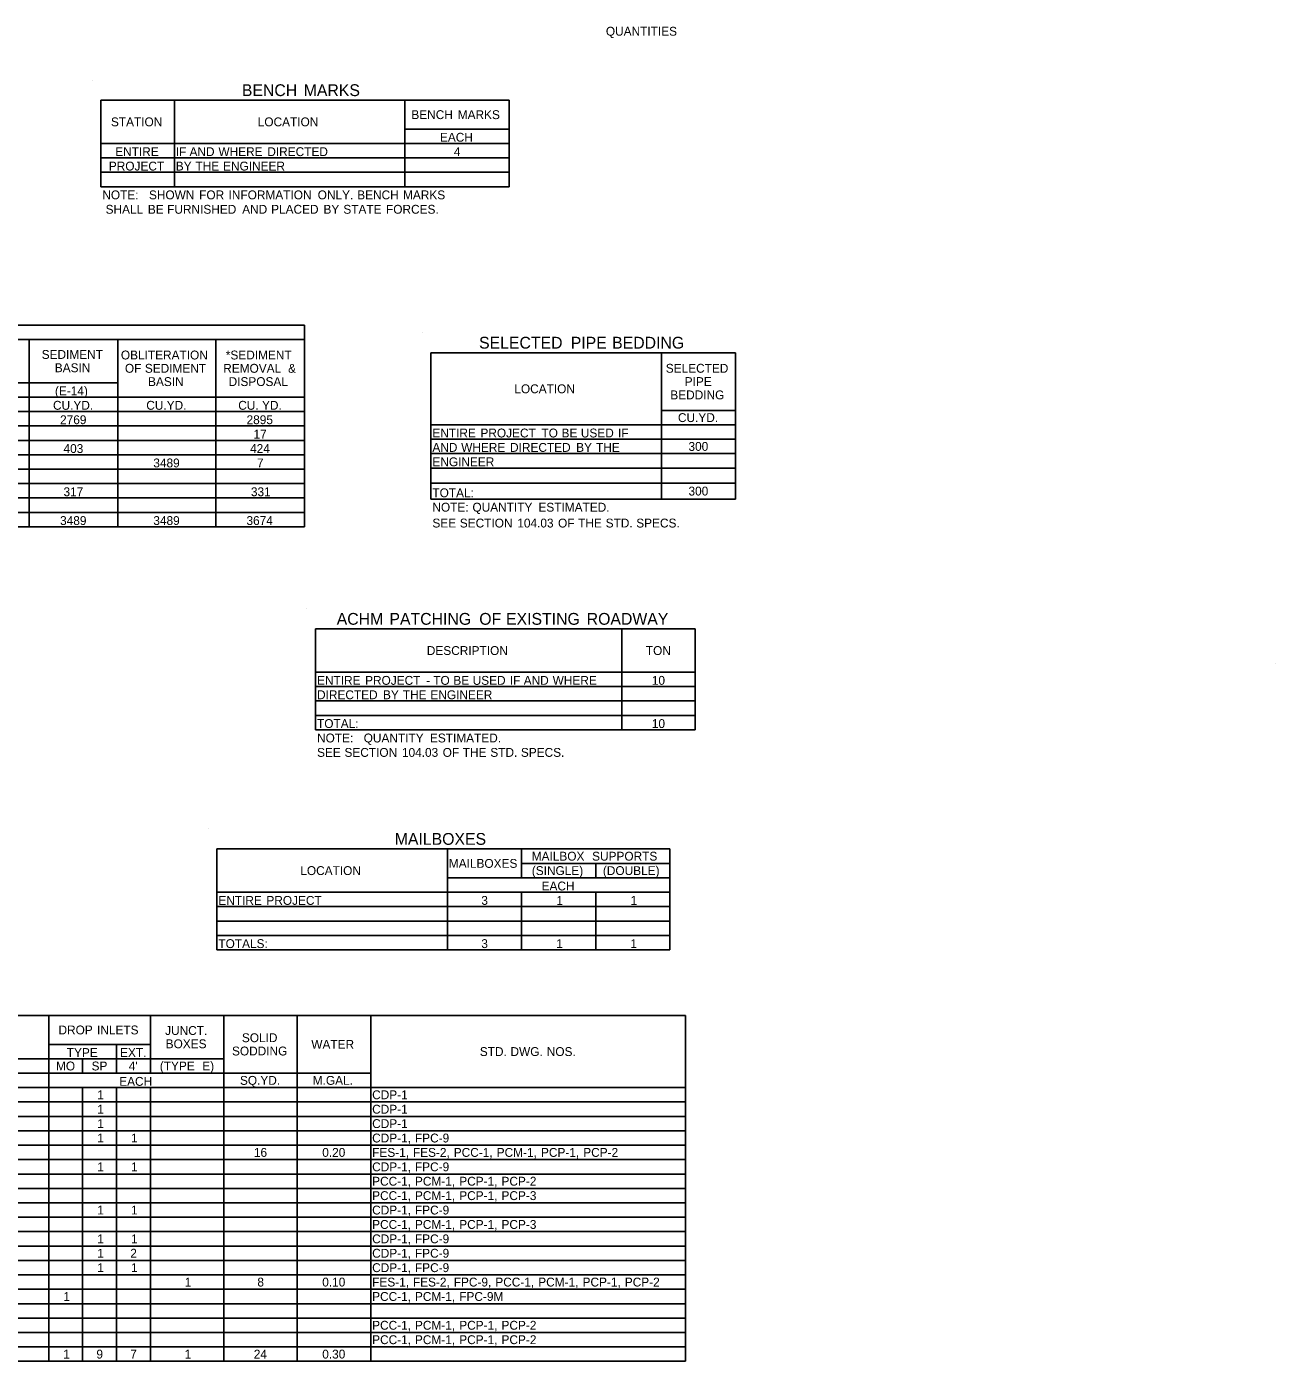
# Model space of a CAD drawing. Extents: x 1197542 to 1207068, y 230488 to 237324.
# Drawn here: x 1200869 to 1201714, y 231809 to 232712 of the extents above; entities that cross this region are included whole.
import ezdxf

# ---------------------------------------------------------------- set-up
doc = ezdxf.new("R2010")
doc.units = 0
doc.layers.add('Default', color=7, linetype='Continuous')
doc.layers.add('R_Border', color=7, linetype='Continuous')

msp = doc.modelspace()

# ---------------------------------------------------------------- linework, layer by layer
at = {"layer": 'Default'}
for p, q in [((1200913.02, 232675.98), (1200913.02, 232675.98)), ((1200918.87, 232662.33), (1201195.29, 232662.33)), ((1200918.87, 232603.83), (1200918.87, 232662.33)), ((1200918.87, 232603.83), (1200918.87, 232662.33)), ((1200968.6, 232603.83), (1200968.6, 232662.33)), ((1201124.6, 232603.83), (1201124.6, 232662.33)), ((1201195.29, 232603.83), (1201195.29, 232662.33)), ((1201124.6, 232642.83), (1201195.29, 232642.83)), ((1201195.29, 232603.83), (1201195.29, 232642.83)), ((1200918.87, 232633.08), (1201195.29, 232633.08)), ((1201124.6, 232603.83), (1201124.6, 232633.08)), ((1200918.87, 232623.33), (1201195.29, 232623.33)), ((1200918.87, 232613.58), (1201195.29, 232613.58)), ((1200918.87, 232603.83), (1201195.29, 232603.83)), ((1199844.22, 232510.16), (1201056.63, 232510.16)), ((1201056.63, 232373.66), (1201056.63, 232510.16)), ((1200165.48, 232500.41), (1201056.63, 232500.41)), ((1200870.4, 232373.66), (1200870.4, 232500.41)), ((1200930.37, 232373.66), (1200930.37, 232500.41)), ((1200996.67, 232373.66), (1200996.67, 232500.41)), ((1201136.44, 232505.07), (1201136.44, 232505.07)), ((1201142.29, 232491.42), (1201348.51, 232491.42)), ((1201142.29, 232392.45), (1201142.29, 232491.42)), ((1201142.29, 232392.45), (1201142.29, 232491.42)), ((1201298.29, 232392.45), (1201298.29, 232491.42)), ((1201348.51, 232392.45), (1201348.51, 232491.42)), ((1201348.51, 232392.45), (1201348.51, 232491.42)), ((1200637.87, 232471.16), (1200930.37, 232471.16)), ((1200820.19, 232471.16), (1200930.37, 232471.16)), ((1200165.48, 232461.41), (1201056.63, 232461.41)), ((1200870.4, 232373.66), (1200870.4, 232461.41)), ((1200930.37, 232461.41), (1201056.63, 232461.41)), ((1200930.37, 232373.66), (1200930.37, 232461.41)), ((1200996.67, 232393.16), (1200996.67, 232461.41)), ((1199844.22, 232451.66), (1201056.63, 232451.66)), ((1201056.63, 232383.41), (1201056.63, 232451.66)), ((1201298.29, 232452.42), (1201348.51, 232452.42)), ((1199844.22, 232441.91), (1201056.63, 232441.91)), ((1201142.29, 232442.67), (1201348.51, 232442.67)), ((1201298.29, 232392.45), (1201298.29, 232442.67)), ((1199844.22, 232432.16), (1201056.63, 232432.16)), ((1201142.29, 232432.92), (1201348.51, 232432.92)), ((1199844.22, 232422.41), (1201056.63, 232422.41)), ((1201142.29, 232423.17), (1201348.51, 232423.17)), ((1199844.22, 232412.66), (1201056.63, 232412.66)), ((1201142.29, 232413.42), (1201348.51, 232413.42)), ((1199844.22, 232402.91), (1201056.63, 232402.91)), ((1201142.29, 232403.18), (1201348.51, 232403.18)), ((1199844.22, 232393.16), (1201056.63, 232393.16)), ((1201142.29, 232392.45), (1201348.51, 232392.45)), ((1199844.22, 232383.41), (1201056.63, 232383.41)), ((1200759.74, 232383.41), (1200996.67, 232383.41)), ((1200996.67, 232383.41), (1201056.63, 232383.41)), ((1200996.67, 232373.66), (1200996.67, 232383.41)), ((1199844.22, 232373.66), (1201056.63, 232373.66)), ((1201058.36, 232318.16), (1201058.36, 232318.16)), ((1201064.21, 232304.51), (1201321.13, 232304.51)), ((1201064.21, 232236.26), (1201064.21, 232304.51)), ((1201064.21, 232236.26), (1201064.21, 232304.51)), ((1201271.4, 232236.26), (1201271.4, 232304.51)), ((1201321.13, 232236.26), (1201321.13, 232304.51)), ((1201064.21, 232275.26), (1201321.13, 232275.26)), ((1201271.4, 232236.26), (1201271.4, 232275.26)), ((1201321.13, 232236.26), (1201321.13, 232275.26)), ((1201713.82, 232281.1), (1201713.82, 232281.1)), ((1201064.21, 232265.51), (1201321.13, 232265.51)), ((1201064.21, 232255.76), (1201321.13, 232255.76)), ((1201064.21, 232246.01), (1201321.13, 232246.01)), ((1201064.21, 232236.26), (1201321.13, 232236.26)), ((1200991.57, 232169.24), (1200991.57, 232169.24)), ((1200997.42, 232155.59), (1201304.06, 232155.59)), ((1200997.42, 232087.34), (1200997.42, 232155.59)), ((1200997.42, 232087.34), (1200997.42, 232155.59)), ((1201153.42, 232087.34), (1201153.42, 232155.59)), ((1201203.63, 232136.09), (1201203.63, 232155.59)), ((1201304.06, 232087.34), (1201304.06, 232155.59)), ((1201203.63, 232145.84), (1201304.06, 232145.84)), ((1201253.85, 232136.09), (1201253.85, 232145.84)), ((1201153.42, 232136.09), (1201304.06, 232136.09)), ((1201203.63, 232136.09), (1201304.06, 232136.09)), ((1200997.42, 232126.34), (1201304.06, 232126.34)), ((1201153.42, 232087.34), (1201153.42, 232126.34)), ((1201203.63, 232087.34), (1201203.63, 232126.34)), ((1201203.63, 232087.34), (1201203.63, 232126.34)), ((1201253.85, 232087.34), (1201253.85, 232126.34)), ((1201253.85, 232087.34), (1201253.85, 232126.34)), ((1201304.06, 232087.34), (1201304.06, 232126.34)), ((1200997.42, 232116.59), (1201304.06, 232116.59)), ((1200997.42, 232106.84), (1201304.06, 232106.84)), ((1200997.42, 232097.09), (1201304.06, 232097.09)), ((1200997.42, 232087.34), (1201304.06, 232087.34)), ((1200342, 232042.86), (1201314.56, 232042.86)), ((1200883.61, 231808.86), (1200883.61, 232042.86)), ((1200952.35, 232003.86), (1200952.35, 232042.86)), ((1200952.35, 232003.86), (1200952.35, 232042.86)), ((1201002.07, 231808.86), (1201002.07, 232042.86)), ((1201051.8, 231808.86), (1201051.8, 232042.86)), ((1201101.52, 231808.86), (1201101.52, 232042.86)), ((1201314.56, 231808.86), (1201314.56, 232042.86)), ((1200883.61, 232023.36), (1200952.35, 232023.36)), ((1200929.43, 232003.86), (1200929.43, 232023.36)), ((1200555.03, 232013.61), (1200952.35, 232013.61)), ((1200883.61, 231808.86), (1200883.61, 232013.61)), ((1200906.52, 232003.86), (1200906.52, 232013.61)), ((1200906.52, 232003.86), (1200906.52, 232013.61)), ((1200929.43, 232003.86), (1200929.43, 232013.61)), ((1200952.35, 232013.61), (1201002.07, 232013.61)), ((1201002.07, 232003.86), (1201002.07, 232013.61)), ((1200504.82, 232003.86), (1200952.35, 232003.86)), ((1200883.61, 232003.86), (1201101.52, 232003.86)), ((1201051.8, 231808.86), (1201051.8, 232003.86)), ((1201101.52, 231808.86), (1201101.52, 232003.86)), ((1200342, 231994.11), (1201314.56, 231994.11)), ((1200906.52, 231808.86), (1200906.52, 231994.11)), ((1200906.52, 231808.86), (1200906.52, 231994.11)), ((1200929.43, 231808.86), (1200929.43, 231994.11)), ((1200929.43, 231808.86), (1200929.43, 231994.11)), ((1200952.35, 231808.86), (1200952.35, 231994.11)), ((1200952.35, 231808.86), (1200952.35, 231994.11)), ((1201002.07, 231808.86), (1201002.07, 231994.11)), ((1201101.52, 231994.11), (1201314.56, 231994.11)), ((1200342, 231984.36), (1201314.56, 231984.36)), ((1201101.52, 231984.36), (1201314.56, 231984.36)), ((1200342, 231974.61), (1201314.56, 231974.61)), ((1201101.52, 231974.61), (1201314.56, 231974.61)), ((1200342, 231964.86), (1201314.56, 231964.86)), ((1200342, 231955.11), (1201314.56, 231955.11)), ((1201101.52, 231955.11), (1201314.56, 231955.11)), ((1200342, 231945.36), (1201314.56, 231945.36)), ((1201101.52, 231945.36), (1201314.56, 231945.36)), ((1200342, 231935.61), (1201314.56, 231935.61)), ((1200342, 231925.86), (1201314.56, 231925.86)), ((1201101.52, 231925.86), (1201314.56, 231925.86)), ((1200342, 231916.11), (1201314.56, 231916.11)), ((1201101.52, 231916.11), (1201314.56, 231916.11)), ((1200342, 231906.36), (1201314.56, 231906.36)), ((1201101.52, 231906.36), (1201314.56, 231906.36)), ((1200342, 231896.61), (1201314.56, 231896.61)), ((1201101.52, 231896.61), (1201314.56, 231896.61)), ((1200342, 231886.86), (1201314.56, 231886.86)), ((1201101.52, 231886.86), (1201314.56, 231886.86)), ((1200342, 231877.11), (1201314.56, 231877.11)), ((1201101.52, 231877.11), (1201314.56, 231877.11)), ((1200342, 231867.36), (1201314.56, 231867.36)), ((1201101.52, 231867.36), (1201314.56, 231867.36)), ((1200342, 231857.61), (1201314.56, 231857.61)), ((1201101.52, 231857.61), (1201314.56, 231857.61)), ((1200342, 231847.86), (1201314.56, 231847.86)), ((1201101.52, 231847.86), (1201314.56, 231847.86)), ((1200342, 231838.11), (1201314.56, 231838.11)), ((1200342, 231828.36), (1201314.56, 231828.36)), ((1201101.52, 231828.36), (1201314.56, 231828.36)), ((1200342, 231818.61), (1201101.52, 231818.61)), ((1201101.52, 231818.61), (1201314.56, 231818.61)), ((1201314.56, 231808.86), (1201314.56, 231818.61)), ((1200342, 231808.86), (1201314.56, 231808.86))]:
    msp.add_line(p, q, dxfattribs=at)

# ---------------------------------------------------------------- texts
for s, height, p in [('BENCH', 8, (1201014.31, 232665.15)), (' MARKS', 8, (1201053.2, 232665.15)), ('BENCH', 6, (1201129.03, 232649.58)), (' MARKS', 6, (1201158.2, 232649.58)), ('STATION', 6, (1200925.68, 232644.7)), ('LOCATION', 6, (1201025.05, 232644.7)), ('EACH', 6, (1201148.39, 232634.28)), ('ENTIRE', 6, (1200928.59, 232624.53)), ('IF', 6, (1200969.57, 232624.53)), (' AND', 6, (1200976.64, 232624.53)), (' WHERE', 6, (1200996.22, 232624.53)), (' DIRECTED', 6, (1201029.31, 232624.53)), ('4', 6, (1201157.82, 232624.53)), ('PROJECT', 6, (1200924.26, 232614.78)), ('BY', 6, (1200969.57, 232614.78)), (' THE', 6, (1200980.7, 232614.78)), (' ENGINEER', 6, (1200999.35, 232614.78)), ('NOTE:', 6, (1200919.85, 232595.28)), ('   SHOWN', 6, (1200944.74, 232595.28)), (' FOR', 6, (1200983.17, 232595.28)), (' INFORMATION', 6, (1201003.08, 232595.28)), (' ONLY.', 6, (1201063.41, 232595.28)), (' BENCH', 6, (1201090.16, 232595.28)), (' MARKS', 6, (1201121.16, 232595.28)), (' SHALL', 6, (1200919.85, 232585.53)), (' BE', 6, (1200948.44, 232585.53)), (' FURNISHED', 6, (1200961.51, 232585.53)), (' AND', 6, (1201012.3, 232585.53)), (' PLACED', 6, (1201031.88, 232585.53)), (' BY', 6, (1201067.31, 232585.53)), (' STATE', 6, (1201080.76, 232585.53)), (' FORCES.', 6, (1201109.66, 232585.53)), ('SELECTED', 8, (1201174.86, 232494.24)), (' PIPE', 8, (1201233.94, 232494.24)), (' BEDDING', 8, (1201261.96, 232494.24)), ('SEDIMENT', 6, (1200878.81, 232487.29)), ('OBLITERATION', 6, (1200932.41, 232486.91)), ('*SEDIMENT', 6, (1201003.44, 232486.91)), ('BASIN', 6, (1200887.68, 232478.29)), ('OF', 6, (1200935.15, 232477.91)), (' SEDIMENT', 6, (1200946.41, 232477.91)), ('REMOVAL', 6, (1201001.69, 232477.91)), (' &', 6, (1201043.36, 232477.91)), ('SELECTED', 6, (1201301.25, 232477.92)), ('BASIN', 6, (1200950.81, 232468.91)), ('DISPOSAL', 6, (1201005.34, 232468.91)), ('PIPE', 6, (1201314.06, 232468.92)), ('(E-14)', 6, (1200887.8, 232462.61)), ('LOCATION', 6, (1201198.74, 232464.04)), ('BEDDING', 6, (1201304.32, 232459.92)), ('CU.YD.', 6, (1200886.47, 232452.86)), ('CU.YD.', 6, (1200949.6, 232452.86)), ('CU.', 6, (1201011.85, 232452.86)), (' YD.', 6, (1201025.71, 232452.86)), ('2769', 6, (1200891.25, 232443.11)), ('2895', 6, (1201017.49, 232443.11)), ('CU.YD.', 6, (1201309.48, 232444.54)), ('17', 6, (1201022.18, 232433.36)), ('ENTIRE', 6, (1201143.27, 232434.12)), (' PROJECT', 6, (1201173.57, 232434.12)), (' TO', 6, (1201214.86, 232434.12)), (' BE', 6, (1201228.45, 232434.12)), (' USED', 6, (1201241.52, 232434.12)), (' IF', 6, (1201266.69, 232434.12)), ('403', 6, (1200893.58, 232423.61)), ('424', 6, (1201019.86, 232423.61)), ('AND', 6, (1201143.27, 232424.37)), (' WHERE', 6, (1201160.52, 232424.37)), (' DIRECTED', 6, (1201193.61, 232424.37)), (' BY', 6, (1201238.35, 232424.37)), (' THE', 6, (1201251.8, 232424.37)), ('300', 6, (1201316.61, 232425.04)), ('3489', 6, (1200954.38, 232413.86)), ('7', 6, (1201024.51, 232413.86)), ('ENGINEER', 6, (1201143.27, 232414.62)), ('317', 6, (1200893.58, 232394.36)), ('331', 6, (1201020.43, 232394.36)), ('TOTAL:', 6, (1201143.27, 232393.65)), ('300', 6, (1201316.62, 232394.82)), ('NOTE:', 6, (1201143.27, 232383.9)), (' QUANTITY', 6, (1201168.16, 232383.9)), (' ESTIMATED.', 6, (1201212.81, 232383.9)), ('3489', 6, (1200891.26, 232374.86)), ('3489', 6, (1200954.39, 232374.86)), ('3674', 6, (1201017.42, 232374.86)), ('SEE', 6, (1201143.27, 232373.18)), (' SECTION', 6, (1201159.6, 232373.18)), (' 104.03', 6, (1201198.51, 232373.18)), (' OF', 6, (1201226.09, 232373.18)), (' THE', 6, (1201239.67, 232373.18)), (' STD.', 6, (1201258.32, 232373.18)), (' SPECS.', 6, (1201279.02, 232373.18)), ('ACHM', 8, (1201078.49, 232307.34)), (' PATCHING', 8, (1201111.22, 232307.34)), (' OF', 8, (1201172.02, 232307.34)), (' EXISTING', 8, (1201190.13, 232307.34)), (' ROADWAY', 8, (1201244.74, 232307.34)), ('DESCRIPTION', 6, (1201139.5, 232286.89)), ('TON', 6, (1201287.75, 232286.89)), ('ENTIRE', 6, (1201065.19, 232266.71)), (' PROJECT', 6, (1201095.49, 232266.71)), (' -', 6, (1201136.78, 232266.71)), (' TO', 6, (1201141.63, 232266.71)), (' BE', 6, (1201155.23, 232266.71)), (' USED', 6, (1201168.3, 232266.71)), (' IF', 6, (1201193.47, 232266.71)), (' AND', 6, (1201202.86, 232266.71)), (' WHERE', 6, (1201222.45, 232266.71)), ('10', 6, (1201291.81, 232266.71)), ('DIRECTED', 6, (1201065.19, 232256.96)), (' BY', 6, (1201107.6, 232256.96)), (' THE', 6, (1201121.05, 232256.96)), (' ENGINEER', 6, (1201139.7, 232256.96)), ('TOTAL:', 6, (1201065.19, 232237.46)), ('10', 6, (1201291.81, 232237.46)), ('NOTE:', 6, (1201065.19, 232227.71)), ('   QUANTITY', 6, (1201090.08, 232227.71)), (' ESTIMATED.', 6, (1201139.38, 232227.71)), ('SEE', 6, (1201065.19, 232217.96)), (' SECTION', 6, (1201081.52, 232217.96)), (' 104.03', 6, (1201120.43, 232217.96)), (' OF', 6, (1201148.01, 232217.96)), (' THE', 6, (1201161.59, 232217.96)), (' STD.', 6, (1201180.24, 232217.96)), (' SPECS.', 6, (1201200.94, 232217.96)), ('MAILBOXES', 8, (1201117.79, 232158.41)), ('MAILBOXES', 6, (1201154.4, 232142.84)), ('MAILBOX', 6, (1201210.5, 232147.71)), (' SUPPORTS', 6, (1201249.15, 232147.71)), ('LOCATION', 6, (1201053.87, 232137.96)), ('(SINGLE)', 6, (1201210.56, 232137.96)), ('(DOUBLE)', 6, (1201258.68, 232137.96)), ('EACH', 6, (1201217.18, 232127.54)), ('ENTIRE', 6, (1200998.4, 232117.79)), (' PROJECT', 6, (1201028.69, 232117.79)), ('3', 6, (1201176.39, 232117.79)), ('1', 6, (1201227.18, 232117.79)), ('1', 6, (1201277.39, 232117.79)), ('TOTALS:', 6, (1200998.4, 232088.54)), ('3', 6, (1201176.38, 232088.54)), ('1', 6, (1201227.09, 232088.54)), ('1', 6, (1201277.3, 232088.54)), ('DROP', 6, (1200890.19, 232030.11)), (' INLETS', 6, (1200914.03, 232030.11)), ('JUNCT.', 6, (1200962.36, 232029.73)), ('SOLID', 6, (1201014.33, 232024.86)), ('TYPE', 6, (1200895.78, 232014.81)), ('EXT.', 6, (1200931.86, 232014.81)), ('BOXES', 6, (1200962.74, 232020.73)), ('SODDING', 6, (1201007.62, 232015.86)), ('WATER', 6, (1201061.31, 232020.36)), ('STD.', 6, (1201175.37, 232015.48)), (' DWG.', 6, (1201193.89, 232015.48)), (' NOS.', 6, (1201218.46, 232015.48)), ('MO', 6, (1200888.48, 232005.73)), ('SP', 6, (1200912.58, 232005.73)), ("4'", 6, (1200937.75, 232005.73)), ('(TYPE', 6, (1200958.77, 232005.73)), ('  E)', 6, (1200983.04, 232005.73)), ('EACH', 6, (1200931.28, 231995.31)), ('SQ.YD.', 6, (1201013.01, 231995.98)), ('M.GAL.', 6, (1201062.28, 231995.98)), ('1', 6, (1200916.42, 231986.23)), ('CDP-1', 6, (1201102.5, 231986.23)), ('1', 6, (1200916.42, 231976.48)), ('CDP-1', 6, (1201102.5, 231976.48)), ('1', 6, (1200916.42, 231966.73)), ('CDP-1', 6, (1201102.5, 231966.73)), ('1', 6, (1200916.42, 231956.98)), ('1', 6, (1200939.33, 231956.98)), ('CDP-1,', 6, (1201102.5, 231956.98)), (' FPC-9', 6, (1201129.23, 231956.98)), ('16', 6, (1201022.46, 231947.23)), ('0.20', 6, (1201068.71, 231947.23)), ('FES-1,', 6, (1201102.5, 231947.23)), (' FES-2,', 6, (1201127.84, 231947.23)), (' PCC-1,', 6, (1201155.5, 231947.23)), (' PCM-1,', 6, (1201184.57, 231947.23)), (' PCP-1,', 6, (1201214.56, 231947.23)), (' PCP-2', 6, (1201243.16, 231947.23)), ('1', 6, (1200916.42, 231937.48)), ('1', 6, (1200939.33, 231937.48)), ('CDP-1,', 6, (1201102.5, 231937.48)), (' FPC-9', 6, (1201129.23, 231937.48)), ('PCC-1,', 6, (1201102.5, 231927.73)), (' PCM-1,', 6, (1201129.23, 231927.73)), (' PCP-1,', 6, (1201159.22, 231927.73)), (' PCP-2', 6, (1201187.82, 231927.73)), ('PCC-1,', 6, (1201102.5, 231917.98)), (' PCM-1,', 6, (1201129.23, 231917.98)), (' PCP-1,', 6, (1201159.22, 231917.98)), (' PCP-3', 6, (1201187.82, 231917.98)), ('1', 6, (1200916.42, 231908.23)), ('1', 6, (1200939.33, 231908.23)), ('CDP-1,', 6, (1201102.5, 231908.23)), (' FPC-9', 6, (1201129.23, 231908.23)), ('PCC-1,', 6, (1201102.5, 231898.48)), (' PCM-1,', 6, (1201129.23, 231898.48)), (' PCP-1,', 6, (1201159.22, 231898.48)), (' PCP-3', 6, (1201187.82, 231898.48)), ('1', 6, (1200916.42, 231888.73)), ('1', 6, (1200939.33, 231888.73)), ('CDP-1,', 6, (1201102.5, 231888.73)), (' FPC-9', 6, (1201129.23, 231888.73)), ('1', 6, (1200916.42, 231878.98)), ('2', 6, (1200938.78, 231878.98)), ('CDP-1,', 6, (1201102.5, 231878.98)), (' FPC-9', 6, (1201129.23, 231878.98)), ('1', 6, (1200916.42, 231869.23)), ('1', 6, (1200939.33, 231869.23)), ('CDP-1,', 6, (1201102.5, 231869.23)), (' FPC-9', 6, (1201129.23, 231869.23)), ('1', 6, (1200975.65, 231859.48)), ('8', 6, (1201024.79, 231859.48)), ('0.10', 6, (1201068.71, 231859.48)), ('FES-1,', 6, (1201102.5, 231859.48)), (' FES-2,', 6, (1201127.84, 231859.48)), (' FPC-9,', 6, (1201155.5, 231859.48)), (' PCC-1,', 6, (1201183.63, 231859.48)), (' PCM-1,', 6, (1201212.7, 231859.48)), (' PCP-1,', 6, (1201242.69, 231859.48)), (' PCP-2', 6, (1201271.29, 231859.48)), ('1', 6, (1200893.5, 231849.73)), ('PCC-1,', 6, (1201102.5, 231849.73)), (' PCM-1,', 6, (1201129.23, 231849.73)), (' FPC-9M', 6, (1201159.22, 231849.73)), ('PCC-1,', 6, (1201102.5, 231830.23)), (' PCM-1,', 6, (1201129.23, 231830.23)), (' PCP-1,', 6, (1201159.22, 231830.23)), (' PCP-2', 6, (1201187.82, 231830.23)), ('PCC-1,', 6, (1201102.5, 231820.48)), (' PCM-1,', 6, (1201129.23, 231820.48)), (' PCP-1,', 6, (1201159.22, 231820.48)), (' PCP-2', 6, (1201187.82, 231820.48)), ('1', 6, (1200893.41, 231810.73)), ('9', 6, (1200915.84, 231810.73)), ('7', 6, (1200938.74, 231810.73)), ('1', 6, (1200975.56, 231810.73)), ('24', 6, (1201022.37, 231810.73)), ('0.30', 6, (1201068.71, 231810.73))]:
    msp.add_text(s, height=height, dxfattribs=at).set_placement(p)
at = {"layer": 'R_Border'}
msp.add_text('QUANTITIES', height=6, rotation=360, dxfattribs=at).set_placement((1201260.7, 232706.03))

doc.saveas('drawing.dxf')
